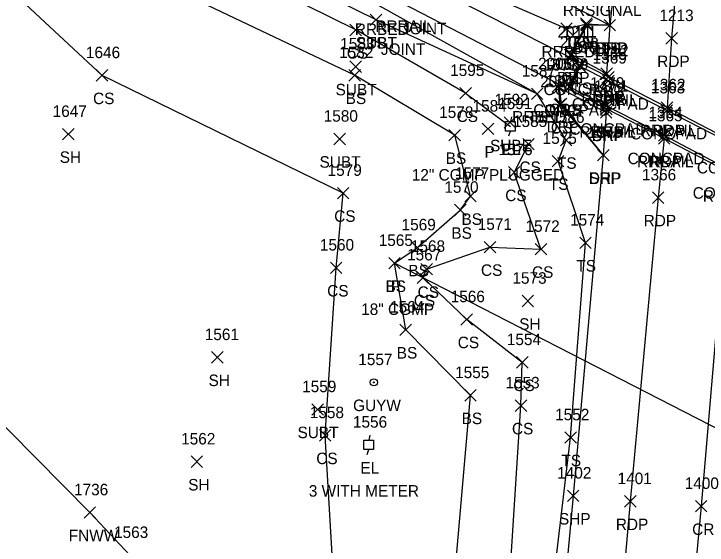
# Model space of a CAD drawing. Extents: x 1443960 to 1446865, y 610387 to 616706.
# Drawn here: x 1446473.8 to 1446594.4, y 611078.2 to 611170.6 of the extents above; entities that cross this region are included whole.
import ezdxf

# ---------------------------------------------------------------- set-up
doc = ezdxf.new("R2010")
doc.units = 0
for name, color, linetype in [('D_A', 7, 'Continuous'), ('D_C', 7, 'Continuous'), ('D_I', 7, 'Continuous'), ('D_TIC', 7, 'Continuous'), ('DCP', 7, 'Continuous'), ('L_A', 7, 'Continuous'), ('L_I', 7, 'Continuous'), ('L_TIC', 7, 'Continuous'), ('LELB', 7, 'Continuous'), ('LFNC', 7, 'Continuous'), ('LS', 7, 'Continuous'), ('P_A', 7, 'Continuous'), ('P_I', 7, 'Continuous'), ('P_TIC', 7, 'Continuous'), ('PET', 7, 'Continuous'), ('PRC', 7, 'Continuous'), ('PSP', 7, 'Continuous'), ('R_A', 7, 'Continuous'), ('R_C', 7, 'Continuous'), ('R_I', 7, 'Continuous'), ('R_TIC', 7, 'Continuous'), ('RDP', 7, 'Continuous'), ('RR', 7, 'Continuous'), ('RRB', 7, 'Continuous'), ('U_A', 7, 'Continuous'), ('U_C', 7, 'Continuous'), ('U_I', 7, 'Continuous'), ('U_TIC', 7, 'Continuous'), ('UEPT', 7, 'Continuous'), ('UPGW', 7, 'Continuous')]:
    doc.layers.add(name, color=color, linetype=linetype)

msp = doc.modelspace()

# ---------------------------------------------------------------- linework, layer by layer
at = {"layer": 'D_TIC'}
for points in [[(1446555.33, 611149.62), (1446557.33, 611151.62)], [(1446557.33, 611149.62), (1446555.33, 611151.62)], [(1446539.05, 611126.24), (1446541.05, 611128.24)], [(1446541.05, 611126.24), (1446539.05, 611128.24)]]:
    msp.add_lwpolyline(points, dxfattribs=at)
at = {"layer": 'DCP'}
msp.add_lwpolyline([(1446632.15, 611079.98), (1446540.05, 611127.24)], dxfattribs=at)
at = {"layer": 'L_TIC'}
for points in [[(1446535.84, 611168.59), (1446537.84, 611170.59)], [(1446537.84, 611168.59), (1446535.84, 611170.59)], [(1446532.31, 611166.82), (1446534.31, 611168.82)], [(1446534.31, 611166.82), (1446532.31, 611168.82)], [(1446572.43, 611167.9), (1446574.43, 611169.9)], [(1446574.43, 611167.9), (1446572.43, 611169.9)], [(1446576.51, 611167.64), (1446578.51, 611169.64)], [(1446578.51, 611167.64), (1446576.51, 611169.64)], [(1446569.62, 611162.47), (1446571.62, 611164.47)], [(1446571.62, 611162.47), (1446569.62, 611164.47)], [(1446571.25, 611160.68), (1446573.25, 611162.68)], [(1446573.25, 611160.68), (1446571.25, 611162.68)], [(1446571.34, 611160.48), (1446573.34, 611162.48)], [(1446573.34, 611160.48), (1446571.34, 611162.48)], [(1446488.18, 611158.91), (1446490.18, 611160.91)], [(1446490.18, 611158.91), (1446488.18, 611160.91)], [(1446532.12, 611158.93), (1446534.12, 611160.93)], [(1446534.12, 611158.93), (1446532.12, 611160.93)], [(1446576.27, 611157.96), (1446578.27, 611159.96)], [(1446578.27, 611157.96), (1446576.27, 611159.96)], [(1446567.5, 611156.99), (1446569.5, 611158.99)], [(1446569.5, 611156.99), (1446567.5, 611158.99)], [(1446569.44, 611156.88), (1446571.44, 611158.88)], [(1446571.44, 611156.88), (1446569.44, 611158.88)], [(1446569.55, 611156.89), (1446571.55, 611158.89)], [(1446571.55, 611156.89), (1446569.55, 611158.89)], [(1446569.55, 611156.89), (1446571.55, 611158.89)], [(1446571.55, 611156.89), (1446569.55, 611158.89)], [(1446551.43, 611155.81), (1446553.43, 611157.81)], [(1446553.43, 611155.81), (1446551.43, 611157.81)], [(1446563.88, 611155.7), (1446565.88, 611157.7)], [(1446565.88, 611155.7), (1446563.88, 611157.7)], [(1446567.82, 611153.85), (1446569.82, 611155.85)], [(1446569.82, 611153.85), (1446567.82, 611155.85)], [(1446575.86, 611153.59), (1446577.86, 611155.59)], [(1446577.86, 611153.59), (1446575.86, 611155.59)], [(1446586.41, 611152.78), (1446588.41, 611154.78)], [(1446588.41, 611152.78), (1446586.41, 611154.78)], [(1446482.33, 611148.69), (1446484.33, 611150.69)], [(1446484.33, 611148.69), (1446482.33, 611150.69)], [(1446549.53, 611148.51), (1446551.53, 611150.51)], [(1446551.53, 611148.51), (1446549.53, 611150.51)], [(1446568.91, 611147.66), (1446570.91, 611149.66)], [(1446570.91, 611147.66), (1446568.91, 611149.66)], [(1446585.97, 611148.47), (1446587.97, 611150.47)], [(1446587.97, 611148.47), (1446585.97, 611150.47)], [(1446562.36, 611146.94), (1446564.36, 611148.94)], [(1446564.36, 611146.94), (1446562.36, 611148.94)], [(1446567.51, 611144), (1446569.51, 611146)], [(1446569.51, 611144), (1446567.51, 611146)], [(1446559.88, 611142.04), (1446561.88, 611144.04)], [(1446561.88, 611142.04), (1446559.88, 611144.04)], [(1446530.13, 611138.44), (1446532.13, 611140.44)], [(1446532.13, 611138.44), (1446530.13, 611140.44)], [(1446552.27, 611137.91), (1446554.27, 611139.91)], [(1446554.27, 611137.91), (1446552.27, 611139.91)], [(1446550.51, 611135.49), (1446552.51, 611137.49)], [(1446552.51, 611135.49), (1446550.51, 611137.49)], [(1446572.29, 611129.79), (1446574.29, 611131.79)], [(1446574.29, 611129.79), (1446572.29, 611131.79)], [(1446543.04, 611128.96), (1446545.04, 611130.96)], [(1446545.04, 611128.96), (1446543.04, 611130.96)], [(1446555.66, 611129.04), (1446557.66, 611131.04)], [(1446557.66, 611129.04), (1446555.66, 611131.04)], [(1446564.54, 611128.7), (1446566.54, 611130.7)], [(1446566.54, 611128.7), (1446564.54, 611130.7)], [(1446539.05, 611126.24), (1446541.05, 611128.24)], [(1446541.05, 611126.24), (1446539.05, 611128.24)], [(1446528.9, 611125.45), (1446530.9, 611127.45)], [(1446530.9, 611125.45), (1446528.9, 611127.45)], [(1446544.64, 611125.22), (1446546.64, 611127.22)], [(1446546.64, 611125.22), (1446544.64, 611127.22)], [(1446543.98, 611123.73), (1446545.98, 611125.73)], [(1446545.98, 611123.73), (1446543.98, 611125.73)], [(1446562.26, 611119.67), (1446564.26, 611121.67)], [(1446564.26, 611119.67), (1446562.26, 611121.67)], [(1446551.62, 611116.46), (1446553.62, 611118.46)], [(1446553.62, 611116.46), (1446551.62, 611118.46)], [(1446541.01, 611114.66), (1446543.01, 611116.66)], [(1446543.01, 611114.66), (1446541.01, 611116.66)], [(1446508.23, 611109.87), (1446510.23, 611111.87)], [(1446510.23, 611109.87), (1446508.23, 611111.87)], [(1446561.29, 611109), (1446563.29, 611111)], [(1446563.29, 611109), (1446561.29, 611111)], [(1446552.29, 611103.25), (1446554.29, 611105.25)], [(1446554.29, 611103.25), (1446552.29, 611105.25)], [(1446561.05, 611101.47), (1446563.05, 611103.47)], [(1446563.05, 611101.47), (1446561.05, 611103.47)], [(1446527.01, 611096.29), (1446529.01, 611098.29)], [(1446529.01, 611096.29), (1446527.01, 611098.29)], [(1446569.69, 611095.92), (1446571.69, 611097.92)], [(1446571.69, 611095.92), (1446569.69, 611097.92)], [(1446504.68, 611091.71), (1446506.68, 611093.71)], [(1446506.68, 611091.71), (1446504.68, 611093.71)], [(1446486.06, 611082.87), (1446488.06, 611084.87)], [(1446488.06, 611082.87), (1446486.06, 611084.87)]]:
    msp.add_lwpolyline(points, dxfattribs=at)
at = {"layer": 'LELB'}
for points in [[(1446591.91, 611396.62), (1446591.29, 611373.02), (1446588.27, 611343.45), (1446585.99, 611302.83), (1446583.49, 611260.98), (1446579.14, 611211.88), (1446577.5, 611193.46), (1446576.67, 611181), (1446577.51, 611168.64)], [(1446548.85, 610888.19), (1446553.44, 610932.22), (1446554.61, 610954.43), (1446557.18, 610985.54), (1446561.83, 611026.07), (1446565.58, 611053.66), (1446570.69, 611096.92), (1446573.29, 611130.79), (1446568.51, 611145), (1446569.91, 611148.66), (1446564.88, 611156.7), (1446536.84, 611169.59), (1446508.69, 611183.48), (1446466.55, 611207.56), (1446427.27, 611227.8), (1446388.8, 611245), (1446349.69, 611268.25), (1446343.09, 611268.96)], [(1446552.43, 611156.81), (1446533.31, 611167.82), (1446507.38, 611180.73), (1446464.69, 611203.31), (1446425.68, 611223.52), (1446387.19, 611242.09), (1446349.13, 611263.69), (1446342.52, 611266.22)], [(1446545.33, 610990.77), (1446549.45, 611028.52), (1446549.03, 611055.59), (1446553.29, 611104.25), (1446542.01, 611115.66), (1446540.05, 611127.24), (1446544.04, 611129.96), (1446551.51, 611136.49), (1446553.27, 611138.91), (1446550.53, 611149.51), (1446533.12, 611159.93), (1446498.33, 611176.52), (1446468.4, 611193.46), (1446432.91, 611211.11), (1446396.49, 611230.29), (1446366.67, 611244.64), (1446348.43, 611256.48)], [(1446530.86, 610991.05), (1446536.61, 611027.8), (1446530.46, 611055.9), (1446528.01, 611097.29), (1446529.9, 611126.45), (1446531.13, 611139.44), (1446489.18, 611159.91), (1446465.02, 611182.42), (1446422.58, 611193.97), (1446390.63, 611222.09), (1446361.12, 611230.87), (1446345.74, 611242.49)], [(1446554.41, 611180.54), (1446577.51, 611168.64)], [(1446573.43, 611168.9), (1446570.62, 611163.47)], [(1446573.43, 611168.9), (1446577.51, 611168.64)], [(1446572.25, 611161.68), (1446570.44, 611157.88)], [(1446568.5, 611157.99), (1446568.82, 611154.85)], [(1446552.43, 611156.81), (1446560.22, 611151.05)], [(1446568.82, 611154.85), (1446576.38, 611146.03)], [(1446552.56, 610989.66), (1446556.82, 611027.38), (1446558.99, 611054.38), (1446562.05, 611102.47), (1446562.29, 611110), (1446552.62, 611117.46), (1446544.98, 611124.73), (1446545.64, 611126.22), (1446556.66, 611130.04), (1446565.54, 611129.7), (1446560.88, 611143.04), (1446563.36, 611147.94)]]:
    msp.add_lwpolyline(points, dxfattribs=at)
at = {"layer": 'LFNC'}
for points in [[(1446487.06, 611083.87), (1446458.93, 611112.28), (1446429.85, 611143.59), (1446396.85, 611177.46)], [(1446494.01, 611076.45), (1446487.06, 611083.87)]]:
    msp.add_lwpolyline(points, dxfattribs=at)
at = {"layer": 'LS'}
for points in [[(1446627.75, 611133.02), (1446620.24, 611136.84), (1446611.06, 611141.61), (1446599.02, 611147.86), (1446587.41, 611153.78), (1446577.27, 611158.96), (1446572.34, 611161.48), (1446570.55, 611157.89)], [(1446627.75, 611133.02), (1446625.86, 611129.37), (1446619.25, 611132.78), (1446610.64, 611137.43), (1446598.29, 611143.46), (1446586.97, 611149.47), (1446576.86, 611154.59), (1446570.55, 611157.89)]]:
    msp.add_lwpolyline(points, dxfattribs=at)
at = {"layer": 'P_TIC'}
for points in [[(1446576.51, 611167.64), (1446578.51, 611169.64)], [(1446578.51, 611167.64), (1446576.51, 611169.64)], [(1446587.27, 611165.36), (1446589.27, 611167.36)], [(1446589.27, 611165.36), (1446587.27, 611167.36)], [(1446575.96, 611159.22), (1446577.96, 611161.22)], [(1446577.96, 611159.22), (1446575.96, 611161.22)], [(1446576.27, 611158.61), (1446578.27, 611160.61)], [(1446578.27, 611158.61), (1446576.27, 611160.61)], [(1446575.88, 611152.48), (1446577.88, 611154.48)], [(1446577.88, 611152.48), (1446575.88, 611154.48)], [(1446575.92, 611153.08), (1446577.92, 611155.08)], [(1446577.92, 611153.08), (1446575.92, 611155.08)], [(1446586.47, 611153.32), (1446588.47, 611155.32)], [(1446588.47, 611153.32), (1446586.47, 611155.32)], [(1446585.96, 611147.93), (1446587.96, 611149.93)], [(1446587.96, 611147.93), (1446585.96, 611149.93)], [(1446575.38, 611145.03), (1446577.38, 611147.03)], [(1446577.38, 611145.03), (1446575.38, 611147.03)], [(1446584.91, 611137.65), (1446586.91, 611139.65)], [(1446586.91, 611137.65), (1446584.91, 611139.65)], [(1446570.14, 611085.78), (1446572.14, 611087.78)], [(1446572.14, 611085.78), (1446570.14, 611087.78)], [(1446580.07, 611084.82), (1446582.07, 611086.82)], [(1446582.07, 611084.82), (1446580.07, 611086.82)], [(1446592.4, 611083.97), (1446594.4, 611085.97)], [(1446594.4, 611083.97), (1446592.4, 611085.97)]]:
    msp.add_lwpolyline(points, dxfattribs=at)
at = {"layer": 'PET'}
for points in [[(1446607.25, 611453.94), (1446606.67, 611433.53), (1446604.98, 611393.16), (1446602.22, 611344.38), (1446599.36, 611301.15), (1446596.11, 611259.06), (1446592.2, 611211.24), (1446588.27, 611166.36), (1446587.47, 611154.32)], [(1446586.96, 611148.93), (1446585.91, 611138.65), (1446581.07, 611085.82), (1446577.8, 611049), (1446573.67, 611008.09), (1446567.43, 610950.16), (1446562.94, 610911.75), (1446557.73, 610863.22), (1446550.26, 610797.89), (1446543.48, 610732.42), (1446535.83, 610665.01), (1446522.7, 610589.27)]]:
    msp.add_lwpolyline(points, dxfattribs=at)
at = {"layer": 'PRC'}
msp.add_lwpolyline([(1446598.39, 611142.94), (1446597.49, 611132.62), (1446593.4, 611084.97), (1446589.92, 611047.69), (1446585, 610993.71), (1446580.73, 610956.9), (1446575.28, 610909.2), (1446570.19, 610861.52)], dxfattribs=at)
at = {"layer": 'PSP'}
for points in [[(1446591.31, 611343.17), (1446588.59, 611302.46), (1446585.58, 611261), (1446582.23, 611211.77), (1446577.51, 611168.64), (1446576.96, 611160.22), (1446577.27, 611159.61)], [(1446576.92, 611154.08), (1446576.88, 611153.48), (1446576.38, 611146.03), (1446571.14, 611086.78), (1446567.69, 611049.79), (1446563.76, 611009.43), (1446561.38, 610989.08), (1446557.86, 610953.83), (1446553.98, 610913.79), (1446549.11, 610862.52), (1446542.65, 610799.79), (1446535.25, 610731.33), (1446527.9, 610668.85), (1446515.47, 610590.43)]]:
    msp.add_lwpolyline(points, dxfattribs=at)
at = {"layer": 'R_TIC'}
for points in [[(1446568.99, 611167.04), (1446570.99, 611169.04)], [(1446570.99, 611167.04), (1446568.99, 611169.04)], [(1446572.5, 611167.66), (1446574.5, 611169.66)], [(1446574.5, 611167.66), (1446572.5, 611169.66)], [(1446576.51, 611167.64), (1446578.51, 611169.64)], [(1446578.51, 611167.64), (1446576.51, 611169.64)], [(1446569.85, 611162.53), (1446571.85, 611164.53)], [(1446571.85, 611162.53), (1446569.85, 611164.53)], [(1446575.96, 611159.22), (1446577.96, 611161.22)], [(1446577.96, 611159.22), (1446575.96, 611161.22)], [(1446576.27, 611158.61), (1446578.27, 611160.61)], [(1446578.27, 611158.61), (1446576.27, 611160.61)], [(1446567.69, 611156.75), (1446569.69, 611158.75)], [(1446569.69, 611156.75), (1446567.69, 611158.75)], [(1446563.88, 611155.7), (1446565.88, 611157.7)], [(1446565.88, 611155.7), (1446563.88, 611157.7)], [(1446568.03, 611153.98), (1446570.03, 611155.98)], [(1446570.03, 611153.98), (1446568.03, 611155.98)], [(1446575.88, 611152.48), (1446577.88, 611154.48)], [(1446577.88, 611152.48), (1446575.88, 611154.48)], [(1446575.92, 611153.08), (1446577.92, 611155.08)], [(1446577.92, 611153.08), (1446575.92, 611155.08)], [(1446586.47, 611153.32), (1446588.47, 611155.32)], [(1446588.47, 611153.32), (1446586.47, 611155.32)], [(1446585.96, 611147.93), (1446587.96, 611149.93)], [(1446587.96, 611147.93), (1446585.96, 611149.93)], [(1446575.38, 611145.03), (1446577.38, 611147.03)], [(1446577.38, 611145.03), (1446575.38, 611147.03)]]:
    msp.add_lwpolyline(points, dxfattribs=at)
at = {"layer": 'RDP'}
for points in [[(1446577.51, 611168.64), (1446573.5, 611168.66), (1446570.85, 611163.53), (1446576.96, 611160.22)], [(1446576.88, 611153.48), (1446568.69, 611157.75), (1446569.03, 611154.98), (1446576.38, 611146.03)]]:
    msp.add_lwpolyline(points, dxfattribs=at)
at = {"layer": 'RR'}
for points in [[(1446830.8, 611028.51), (1446813.8, 611037.34), (1446780.13, 611054.63), (1446766.6, 611061.72), (1446723.16, 611084.18), (1446681.83, 611105.5), (1446667.65, 611112.72), (1446650.45, 611121.75), (1446635.82, 611129.05), (1446620.36, 611137.27), (1446611.04, 611142.08), (1446598.97, 611148.35), (1446587.47, 611154.32), (1446577.27, 611159.61), (1446545.1, 611176.06), (1446537.95, 611179.67), (1446530.32, 611183.72), (1446472.23, 611213.59), (1446430.68, 611235.02), (1446393.22, 611254.19), (1446353.39, 611274.79), (1446345.67, 611278.8)], [(1446830.61, 611022.91), (1446812, 611032.72), (1446777.67, 611050.48), (1446764.9, 611057.05), (1446720.8, 611079.76), (1446679.61, 611101.04), (1446672.6, 611104.75), (1446648.09, 611117.4), (1446634.05, 611124.73), (1446619.04, 611132.42), (1446610.71, 611136.75), (1446598.39, 611142.94), (1446586.96, 611148.93), (1446576.92, 611154.08), (1446541.41, 611172.48), (1446511.36, 611187.89), (1446469.88, 611209.21), (1446428.54, 611230.42), (1446391.04, 611249.76), (1446351.07, 611270.34), (1446343.04, 611274.54)]]:
    msp.add_lwpolyline(points, dxfattribs=at)
at = {"layer": 'RRB'}
for points in [[(1446569.99, 611168.04), (1446545.96, 611178.46), (1446513.02, 611195.82), (1446473.29, 611215.85), (1446431.72, 611237.21), (1446394.07, 611256.06), (1446354.34, 611276.82), (1446346.71, 611281.18)], [(1446564.88, 611156.7), (1446537.51, 611171.94), (1446510.38, 611186.08), (1446466.95, 611208.66), (1446427.98, 611228.69), (1446390.24, 611247.7), (1446350.09, 611268.94), (1446342.68, 611272.23)], [(1446569.99, 611168.04), (1446573.43, 611168.9)]]:
    msp.add_lwpolyline(points, dxfattribs=at)
at = {"layer": 'U_TIC'}
for points in [[(1446535.84, 611168.59), (1446537.84, 611170.59)], [(1446537.84, 611168.59), (1446535.84, 611170.59)], [(1446532.31, 611160.44), (1446534.31, 611162.44)], [(1446534.31, 611160.44), (1446532.31, 611162.44)], [(1446559.15, 611150.71), (1446561.15, 611152.71)], [(1446561.15, 611150.71), (1446559.15, 611152.71)], [(1446529.52, 611147.86), (1446531.52, 611149.86)], [(1446531.52, 611147.86), (1446529.52, 611149.86)], [(1446525.69, 611100.81), (1446527.69, 611102.81)], [(1446527.69, 611100.81), (1446525.69, 611102.81)]]:
    msp.add_lwpolyline(points, dxfattribs=at)
at = {"layer": 'UEPT'}
for p, q in [((1446559.39, 611150.21), (1446559.39, 611151.88)), ((1446559.39, 611151.88), (1446561.05, 611151.88)), ((1446560.39, 611152.71), (1446560.22, 611151.88)), ((1446561.05, 611151.88), (1446561.05, 611150.21)), ((1446560.22, 611151.05), (1446560.22, 611151.05)), ((1446561.05, 611150.21), (1446559.39, 611150.21)), ((1446559.97, 611149.38), (1446560.22, 611150.21)), ((1446534.75, 611094.81), (1446534.75, 611096.48)), ((1446534.75, 611096.48), (1446536.41, 611096.48)), ((1446535.75, 611097.31), (1446535.58, 611096.48)), ((1446536.41, 611096.48), (1446536.41, 611094.81)), ((1446535.58, 611095.64), (1446535.58, 611095.64)), ((1446536.41, 611094.81), (1446534.75, 611094.81)), ((1446535.33, 611093.98), (1446535.58, 611094.81))]:
    msp.add_line(p, q, dxfattribs=at)
at = {"layer": 'UPGW'}
for radius in [0.625, 0.0833]:
    msp.add_circle((1446536.46, 611106.52), radius, dxfattribs=at)

# ---------------------------------------------------------------- texts
at = {"layer": 'D_A'}
for p in [(1446555.71, 611145.62), (1446539.43, 611122.24)]:
    msp.add_text('P', height=2, dxfattribs=at).set_placement(p)
at = {"layer": 'D_C'}
for s, p in [('12" CGMP PLUGGED', (1446543.06, 611141.62)), ('18" CGMP', (1446534.26, 611118.24))]:
    msp.add_text(s, height=2, dxfattribs=at).set_placement(p)
at = {"layer": 'D_I'}
for s, p in [('1584', (1446553.63, 611153.62)), ('1565', (1446537.31, 611130.24))]:
    msp.add_text(s, height=2, dxfattribs=at).set_placement(p)
at = {"layer": 'L_A'}
for s, p in [('TS', (1446535.25, 611164.59)), ('CS', (1446571.87, 611163.9)), ('TS', (1446575.92, 611163.64)), ('CS', (1446531.75, 611162.82)), ('CS', (1446569.06, 611158.47)), ('CONCPAD', (1446565.99, 611156.48)), ('CS', (1446570.69, 611156.68)), ('CS', (1446487.62, 611154.91)), ('BS', (1446531.56, 611154.93)), ('CONCPAD', (1446570.92, 611153.96)), ('CONCPAD', (1446564.2, 611152.89)), ('CONCPAD', (1446564.2, 611152.89)), ('CS', (1446566.94, 611152.99)), ('CS', (1446568.88, 611152.88)), ('CS', (1446550.87, 611151.81)), ('TS', (1446563.29, 611151.7)), ('CS', (1446567.26, 611149.85)), ('CONCPAD', (1446570.5, 611149.59)), ('CONCPAD', (1446581.06, 611148.78)), ('SH', (1446481.82, 611144.69)), ('BS', (1446548.97, 611144.51)), ('CONCPAD', (1446580.61, 611144.47)), ('CS', (1446561.8, 611142.94)), ('TS', (1446568.32, 611143.66)), ('CONCPAD', (1446592.67, 611142.86)), ('TS', (1446566.92, 611140)), ('CS', (1446559.32, 611138.04)), ('CONCPAD', (1446591.94, 611138.46)), ('CS', (1446529.57, 611134.44)), ('BS', (1446551.71, 611133.91)), ('BS', (1446549.95, 611131.49)), ('TS', (1446571.7, 611125.79)), ('BS', (1446542.48, 611124.96)), ('CS', (1446555.1, 611125.04)), ('CS', (1446563.98, 611124.7)), ('BS', (1446538.49, 611122.24)), ('CS', (1446528.35, 611121.45)), ('CS', (1446544.08, 611121.22)), ('CS', (1446543.42, 611119.73)), ('SH', (1446561.75, 611115.67)), ('CS', (1446551.06, 611112.46)), ('BS', (1446540.45, 611110.66)), ('SH', (1446507.71, 611105.87)), ('CS', (1446560.73, 611105)), ('BS', (1446551.74, 611099.25)), ('CS', (1446560.49, 611097.47)), ('CS', (1446526.45, 611092.29)), ('TS', (1446569.1, 611091.92)), ('SH', (1446504.17, 611087.71)), ('FNWW', (1446483.4, 611078.87))]:
    msp.add_text(s, height=2, dxfattribs=at).set_placement(p)
at = {"layer": 'L_I'}
for s, p in [('2011', (1446568.41, 611166.47)), ('2008', (1446568.84, 611164.68)), ('1588', (1446569.65, 611164.48)), ('1646', (1446486.38, 611162.91)), ('1582', (1446530.42, 611162.93)), ('1369', (1446574.52, 611161.96)), ('2006', (1446565.03, 611160.99)), ('2009', (1446567.01, 611160.88)), ('1589', (1446567.85, 611160.89)), ('1589', (1446567.85, 611160.89)), ('1595', (1446549.74, 611159.81)), ('1587', (1446562.19, 611159.7)), ('2007', (1446565.41, 611157.85)), ('1370', (1446574.08, 611157.59)), ('1363', (1446584.67, 611156.78)), ('1647', (1446480.59, 611152.69)), ('1578', (1446547.83, 611152.51)), ('1364', (1446584.23, 611152.47)), ('1586', (1446567.17, 611151.66)), ('1585', (1446560.67, 611150.94)), ('1575', (1446565.82, 611148)), ('1576', (1446558.13, 611146.04)), ('1579', (1446528.42, 611142.44)), ('1577', (1446550.58, 611141.91)), ('1570', (1446548.73, 611139.49)), ('1569', (1446541.29, 611132.96)), ('1571', (1446554.53, 611133.04)), ('1574', (1446570.6, 611133.79)), ('1572', (1446562.85, 611132.7)), ('1560', (1446527.08, 611129.45)), ('1565', (1446537.31, 611130.24)), ('1568', (1446542.9, 611129.22)), ('1567', (1446542.24, 611127.73)), ('1573', (1446560.57, 611123.67)), ('1566', (1446549.83, 611120.46)), ('1564', (1446539.27, 611118.66)), ('1561', (1446507.05, 611113.87)), ('1554', (1446559.6, 611113)), ('1555', (1446550.6, 611107.25)), ('1553', (1446559.36, 611105.47)), ('1558', (1446525.32, 611100.29)), ('1552', (1446568, 611099.92)), ('1562', (1446502.94, 611095.71)), ('1736', (1446484.31, 611086.87)), ('1563', (1446491.27, 611079.45))]:
    msp.add_text(s, height=2, dxfattribs=at).set_placement(p)
at = {"layer": 'P_A'}
for s, p in [('SHP', (1446575.04, 611163.64)), ('RDP', (1446585.76, 611161.36)), ('SHP', (1446574.49, 611155.22)), ('SHP', (1446574.8, 611154.61)), ('SHP', (1446574.46, 611149.08)), ('RDP', (1446584.96, 611149.32)), ('SHP', (1446574.41, 611148.48)), ('RDP', (1446584.45, 611143.93)), ('SHP', (1446573.92, 611141.03)), ('RDP', (1446583.4, 611133.65)), ('SHP', (1446568.67, 611081.78)), ('RDP', (1446578.56, 611080.82)), ('CR', (1446591.84, 611079.97))]:
    msp.add_text(s, height=2, dxfattribs=at).set_placement(p)
at = {"layer": 'P_I'}
for s, p in [('1213', (1446586.14, 611169.36)), ('1212', (1446574.83, 611163.22)), ('1368', (1446574.53, 611162.61)), ('1371', (1446574.79, 611157.08)), ('1362', (1446584.73, 611157.32)), ('1372', (1446574.19, 611156.48)), ('1365', (1446584.22, 611151.93)), ('1375', (1446573.69, 611149.03)), ('1366', (1446583.11, 611141.65)), ('1402', (1446568.36, 611089.78)), ('1401', (1446578.87, 611088.82)), ('1400', (1446590.54, 611087.97))]:
    msp.add_text(s, height=2, dxfattribs=at).set_placement(p)
at = {"layer": 'R_A'}
for s, p in [('RRSIGNAL', (1446569.35, 611170.26)), ('RRBED', (1446533.16, 611166.94)), ('RRRAIL', (1446536.71, 611167.48)), ('DRP', (1446570.99, 611163.66)), ('DRP', (1446575, 611163.64)), ('RRBED', (1446565.64, 611163.04)), ('DRP', (1446568.34, 611158.53)), ('DRP', (1446574.44, 611155.22)), ('RRRAIL', (1446572.56, 611154.61)), ('DRP', (1446566.18, 611152.75)), ('RRBED', (1446560.53, 611151.7)), ('DRP', (1446566.52, 611149.98)), ('RRRAIL', (1446572.21, 611149.08)), ('RRRAIL', (1446582.76, 611149.32)), ('DRP', (1446574.37, 611148.48)), ('RRRAIL', (1446582.25, 611143.93)), ('DRP', (1446573.87, 611141.03)), ('RRRAIL', (1446593.69, 611137.94))]:
    msp.add_text(s, height=2, dxfattribs=at).set_placement(p)
at = {"layer": 'R_C'}
for p in [(1446541.37, 611167.06), (1446537.69, 611163.48)]:
    msp.add_text('JOINT', height=2, dxfattribs=at).set_placement(p)
at = {"layer": 'R_I'}
for s, p in [('1211', (1446569.29, 611166.53)), ('1212', (1446574.83, 611163.22)), ('1368', (1446574.53, 611162.61)), ('1373', (1446566, 611160.75)), ('1587', (1446562.19, 611159.7)), ('1374', (1446566.34, 611157.98)), ('1371', (1446574.79, 611157.08)), ('1362', (1446584.73, 611157.32)), ('1372', (1446574.19, 611156.48)), ('1365', (1446584.22, 611151.93)), ('1375', (1446573.69, 611149.03))]:
    msp.add_text(s, height=2, dxfattribs=at).set_placement(p)
at = {"layer": 'U_A'}
for s, p in [('SUBT', (1446533.34, 611164.59)), ('SUBT', (1446529.81, 611156.44)), ('SUBE', (1446556.68, 611146.71)), ('EL', (1446558.76, 611146.05)), ('SUBT', (1446527.02, 611143.86)), ('GUYW', (1446532.85, 611101.52)), ('SUBT', (1446523.19, 611096.81)), ('EL', (1446534.12, 611090.64))]:
    msp.add_text(s, height=2, dxfattribs=at).set_placement(p)
at = {"layer": 'U_C'}
msp.add_text('3 WITH METER', height=2, dxfattribs=at).set_placement((1446525.15, 611086.64))
at = {"layer": 'U_I'}
for s, p in [('1583', (1446530.62, 611164.44)), ('1592', (1446557.46, 611154.71)), ('1591', (1446558.09, 611154.05)), ('1580', (1446527.74, 611151.86)), ('1557', (1446533.76, 611109.52)), ('1559', (1446523.99, 611104.81)), ('1556', (1446532.83, 611098.64))]:
    msp.add_text(s, height=2, dxfattribs=at).set_placement(p)

doc.saveas('drawing.dxf')
